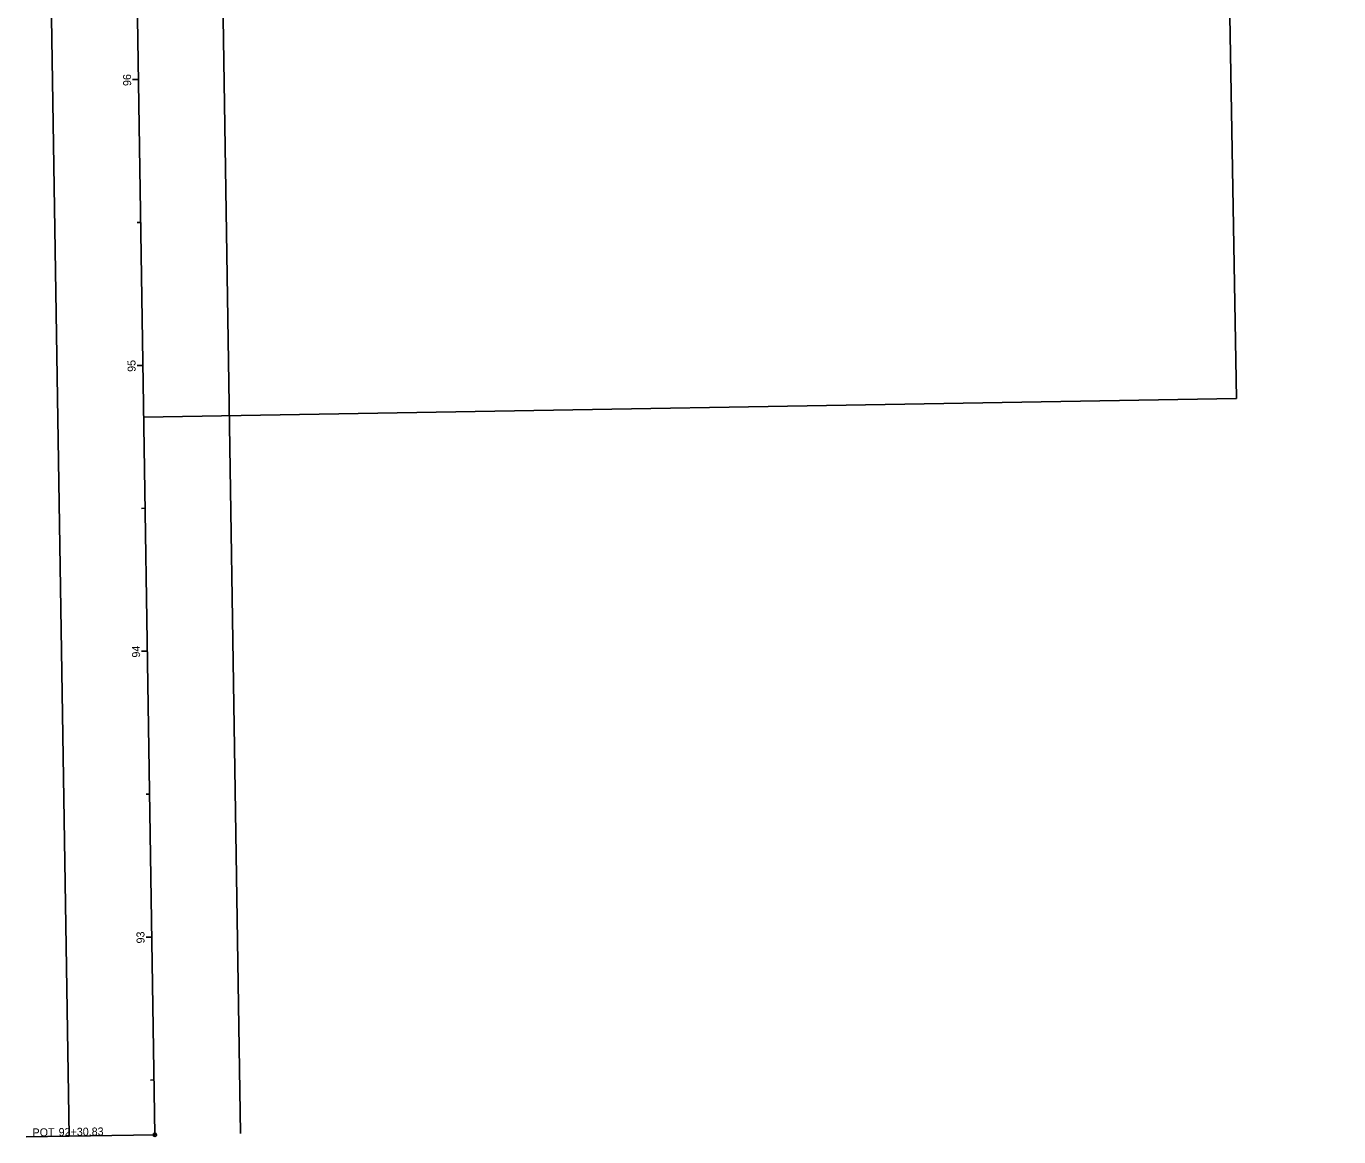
# Model space of a CAD drawing. Extents: x 2345526 to 2352728, y 625359 to 628213.
# Drawn here: x 2350627.4 to 2351086.5, y 625359.2 to 625747.7 of the extents above; entities that cross this region are included whole.
import ezdxf

# ---------------------------------------------------------------- set-up
doc = ezdxf.new("R2010")
doc.units = 0
for name, color, linetype in [('DR_P_Ditch', 7, 'Continuous'), ('DR_P_Headwall', 7, 'Continuous'), ('DR_X_Cells', 7, 'Continuous'), ('DR_X_Ditch', 7, 'Continuous'), ('DR_X_GenericNode', 7, 'Continuous'), ('DR_X_Storm_Sewer', 7, 'Continuous'), ('GE_P_Alignment', 7, 'Continuous'), ('GK_Drainage_Nodes', 7, 'Continuous'), ('SC_Scratch1', 7, 'Continuous')]:
    doc.layers.add(name, color=color, linetype=linetype)

msp = doc.modelspace()

# ---------------------------------------------------------------- linework, layer by layer
at = {"layer": 'DR_P_Ditch'}
msp.add_line((2350672.35, 625359.95), (2350647.92, 626920.89), dxfattribs=at)
at = {"layer": 'DR_P_Headwall'}
msp.add_line((2350668.14, 625629.08), (2350666.94, 625629.06), dxfattribs=at)
at = {"layer": 'DR_X_Cells'}
msp.add_line((2350672.35, 625359.95), (2350627.36, 625359.25), dxfattribs=at)
msp.add_circle((2350672.35, 625359.95), 0.6, dxfattribs=at)
at = {"layer": 'DR_X_Ditch'}
msp.add_line((2350672.35, 625359.95), (2350627.36, 625359.25), dxfattribs=at)
msp.add_circle((2350672.35, 625359.95), 0.6, dxfattribs=at)
at = {"layer": 'DR_X_GenericNode'}
for p, q in [((2350630.63, 626108.69), (2350642.36, 625359.48)), ((2350691.02, 626084.19), (2350702.35, 625360.42))]:
    msp.add_line(p, q, dxfattribs=at)
at = {"layer": 'DR_X_Storm_Sewer'}
for p, q in [((2351050.65, 625617.48), (2351044.6, 625974.12)), ((2350668.42, 625611), (2351050.65, 625617.48))]:
    msp.add_line(p, q, dxfattribs=at)
msp.add_arc((2357342.83, 641967.55), 17188.88, 247.922783, 252.089433, dxfattribs=at)
at = {"layer": 'GE_P_Alignment'}
msp.add_line((2350672.35, 625359.95), (2350627.36, 625359.25), dxfattribs=at)
msp.add_circle((2350672.35, 625359.95), 0.6, dxfattribs=at)
at = {"layer": 'GK_Drainage_Nodes'}
for p, q in [((2350666.57, 625729.07), (2350665.37, 625729.05)), ((2350668.14, 625629.08), (2350666.14, 625629.05)), ((2350669.7, 625529.1), (2350668.51, 625529.08)), ((2350671.27, 625429.11), (2350670.07, 625429.09))]:
    msp.add_line(p, q, dxfattribs=at)
at = {"layer": 'SC_Scratch1'}
for p, q in [((2350666.57, 625729.07), (2350664.57, 625729.04)), ((2350667.36, 625679.08), (2350666.16, 625679.06)), ((2350668.14, 625629.08), (2350666.14, 625629.05)), ((2350668.92, 625579.09), (2350667.72, 625579.07)), ((2350669.7, 625529.1), (2350667.71, 625529.06)), ((2350670.49, 625479.1), (2350669.29, 625479.08)), ((2350671.27, 625429.11), (2350669.27, 625429.08)), ((2350672.05, 625379.11), (2350670.85, 625379.09))]:
    msp.add_line(p, q, dxfattribs=at)

# ---------------------------------------------------------------- texts
at = {"layer": 'DR_X_Cells'}
for s, p in [('POT', (2350629.58, 625359.33)), ('92+30.83', (2350638.71, 625359.47))]:
    msp.add_text(s, height=2.8, rotation=0.8969, dxfattribs=at).set_placement(p)
at = {"layer": 'DR_X_Ditch'}
for s, p in [('POT', (2350629.58, 625359.33)), ('92+30.83', (2350638.71, 625359.47))]:
    msp.add_text(s, height=2.8, rotation=0.8969, dxfattribs=at).set_placement(p)
at = {"layer": 'GE_P_Alignment'}
for s, p in [('POT', (2350629.58, 625359.33)), ('92+30.83', (2350638.71, 625359.47))]:
    msp.add_text(s, height=2.8, rotation=0.8969, dxfattribs=at).set_placement(p)
at = {"layer": 'GK_Drainage_Nodes'}
msp.add_text('95', height=2.8, rotation=90.8969, dxfattribs=at).set_placement((2350665.63, 625626.84))
at = {"layer": 'SC_Scratch1'}
for s, p in [('96', (2350664.06, 625726.83)), ('95', (2350665.63, 625626.84)), ('94', (2350667.19, 625526.9)), ('93', (2350668.76, 625426.89))]:
    msp.add_text(s, height=2.8, rotation=90.8969, dxfattribs=at).set_placement(p)

doc.saveas('drawing.dxf')
